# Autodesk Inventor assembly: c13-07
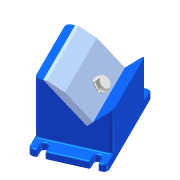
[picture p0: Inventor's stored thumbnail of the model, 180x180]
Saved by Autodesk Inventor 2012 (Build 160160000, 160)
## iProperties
Created: 2010-11
Part Number: c13-07
Document SubType Name: Assembly
Designer: Beta-8540w
Author: Beta-8540w
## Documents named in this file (5)
- C:\Users\VMuser\Desktop\Inventor 2012 Essentials\Assemblies\Chapter 13\c13-07.iam
- C:\Users\VMuser\Desktop\Inventor 2012 Essentials\Content Center Files\en-US\ISO 4017\ISO 4017 - M10 x 35ISO.ipt
- C:\Users\VMuser\Desktop\Inventor 2012 Essentials\Parts\Chapter 13\c13-02.ipt
- C:\Users\VMuser\Desktop\Inventor 2012 Essentials\Content Center Files\en-US\ISO 7091\ISO 7091 - ST 10 - 100 HV.ipt
- C:\Users\VMuser\Desktop\Inventor 2012 Essentials\Parts\Chapter 13\c13-01.ipt
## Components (4 placed, 4 different names)
1. c13-01:1 — Insert:1, Angle:1
2. c13-02:1 — Insert:1, Angle:1, Insert:2
3. ISO 4017 M10 x 35:1 — Insert:3, Bolt Angle
4. ISO 7091 ST 10 - 100 HV:1 — Insert:2, Insert:3
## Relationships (5: Insert 3, Angle 2)
- Insert:1: c13-01:1 ↔ c13-02:1
- Angle:1: c13-01:1 ↔ c13-02:1
- Insert:2: c13-02:1 ↔ ISO 7091 ST 10 - 100 HV:1
- Insert:3: ISO 4017 M10 x 35:1 ↔ ISO 7091 ST 10 - 100 HV:1
- Bolt Angle [Angle]: ISO 4017 M10 x 35:1
